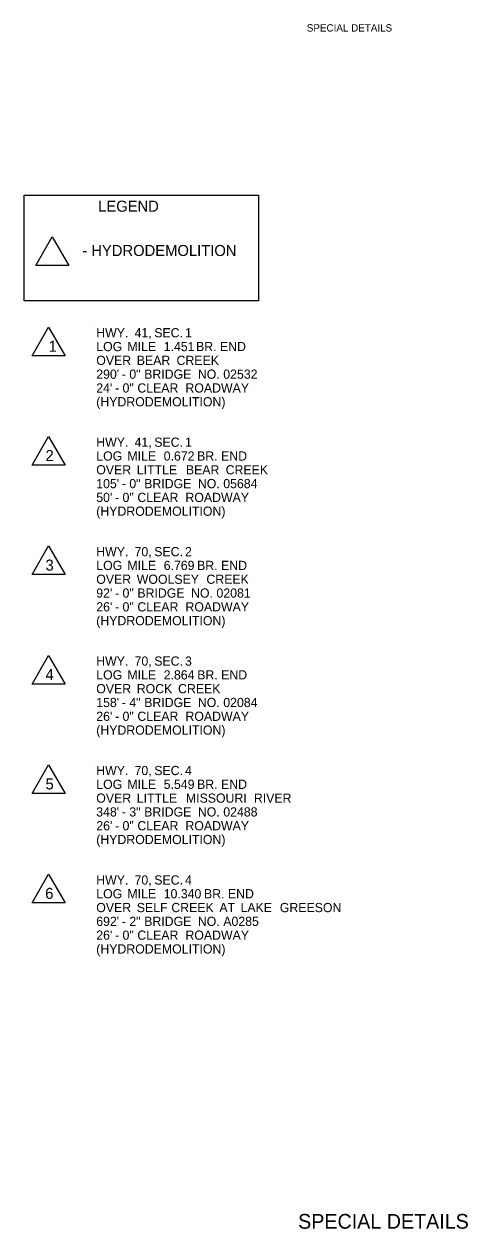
# Model space of a CAD drawing. Extents: x -17742 to 32032, y -17264 to 5867.
# Drawn here: x -5718 to -2101, y -4264 to 5557 of the extents above; entities that cross this region are included whole.
import ezdxf

# ---------------------------------------------------------------- set-up
doc = ezdxf.new("R2010")
doc.units = 0
for name, color, linetype in [('Default', 7, 'Continuous'), ('R_Annotation', 7, 'Continuous'), ('R_Border', 7, 'Continuous')]:
    doc.layers.add(name, color=color, linetype=linetype)

msp = doc.modelspace()

# ---------------------------------------------------------------- linework, layer by layer
at = {"layer": 'R_Annotation'}
for p, q in [((-5144.6, 3093.7), (-5144.6, 3093.7)), ((-5144.6, -474.8), (-5144.6, -474.8))]:
    msp.add_line(p, q, dxfattribs=at)
for points in [[(-5718.1, 4163.9), (-3807.5, 4163.9), (-3807.5, 3302.6), (-5718.1, 3302.6)], [(-5488.8, 3824.1), (-5353.8, 3590.3), (-5623.8, 3590.3)], [(-5517.9, 3087.5), (-5382.9, 2853.7), (-5652.9, 2853.7)], [(-5517.9, 2196.3), (-5382.9, 1962.5), (-5652.9, 1962.5)], [(-5517.9, 1303.3), (-5382.9, 1069.5), (-5652.9, 1069.5)], [(-5517.9, 411.2), (-5382.9, 177.3), (-5652.9, 177.3)], [(-5517.9, -481), (-5382.9, -714.8), (-5652.9, -714.8)], [(-5517.9, -1373.1), (-5382.9, -1606.9), (-5652.9, -1606.9)]]:
    msp.add_lwpolyline(points, close=True, dxfattribs=at)

# ---------------------------------------------------------------- texts
at = {"layer": 'Default'}
for s, p in [('HWY.', (-5130, 3003.7)), (' 41,', (-4845.7, 3003.7)), (' SEC.', (-4685.2, 3003.7)), (' 1', (-4434.6, 3003.7)), ('LOG', (-5130, 2891.2)), (' MILE', (-4904, 2891.2)), (' 1.451', (-4608.2, 2891.2)), (' BR.', (-4344.8, 2891.2)), (' END', (-4149.6, 2891.2)), ('OVER', (-5130, 2778.7)), (' BEAR', (-4827.6, 2778.7)), (' CREEK', (-4503.5, 2778.7)), ("290'", (-5130, 2666.2)), (' -', (-4948.5, 2666.2)), (' 0"', (-4888.3, 2666.2)), (' BRIDGE', (-4767.3, 2666.2)), (' NO.', (-4329.9, 2666.2)), (' 02532', (-4122.5, 2666.2)), ("24'", (-5130, 2553.7)), (' -', (-5003.9, 2553.7)), (' 0"', (-4943.7, 2553.7)), (' CLEAR', (-4822.7, 2553.7)), (' ROADWAY', (-4431, 2553.7)), ('(HYDRODEMOLITION)', (-5130, 2441.2)), ('HWY.', (-5130, 2111.6)), (' 41,', (-4845.7, 2111.6)), (' SEC.', (-4685.2, 2111.6)), (' 1', (-4434.6, 2111.6)), ('LOG', (-5130, 1999.1)), (' MILE', (-4904, 1999.1)), (' 0.672', (-4608.2, 1999.1)), (' BR.', (-4335.9, 1999.1)), (' END', (-4140.6, 1999.1)), ('OVER', (-5130, 1886.6)), (' LITTLE', (-4827.6, 1886.6)), (' BEAR', (-4427.3, 1886.6)), (' CREEK', (-4103.3, 1886.6)), ("105'", (-5130, 1774.1)), (' -', (-4948.5, 1774.1)), (' 0"', (-4888.3, 1774.1)), (' BRIDGE', (-4767.3, 1774.1)), (' NO.', (-4329.9, 1774.1)), (' 05684', (-4122.5, 1774.1)), ("50'", (-5130, 1661.6)), (' -', (-5003.9, 1661.6)), (' 0"', (-4943.7, 1661.6)), (' CLEAR', (-4822.7, 1661.6)), (' ROADWAY', (-4431, 1661.6)), ('(HYDRODEMOLITION)', (-5130, 1549.1)), ('HWY.', (-5130, 1219.5)), (' 70,', (-4845.7, 1219.5)), (' SEC.', (-4685.2, 1219.5)), (' 2', (-4434.6, 1219.5)), ('LOG', (-5130, 1107)), (' MILE', (-4904, 1107)), (' 6.769', (-4608.2, 1107)), (' BR.', (-4336, 1107)), (' END', (-4140.7, 1107)), ('OVER', (-5130, 994.5)), (' WOOLSEY', (-4827.6, 994.5)), (' CREEK', (-4260.1, 994.5)), ("92'", (-5130, 882)), (' -', (-5003.9, 882)), (' 0"', (-4943.7, 882)), (' BRIDGE', (-4822.7, 882)), (' NO.', (-4385.3, 882)), (' 02081', (-4177.9, 882)), ("26'", (-5130, 769.5)), (' -', (-5003.9, 769.5)), (' 0"', (-4943.7, 769.5)), (' CLEAR', (-4822.7, 769.5)), (' ROADWAY', (-4431, 769.5)), ('(HYDRODEMOLITION)', (-5130, 657)), ('HWY.', (-5130, 327.3)), (' 70,', (-4845.7, 327.3)), (' SEC.', (-4685.2, 327.3)), (' 3', (-4434.6, 327.3)), ('LOG', (-5130, 214.8)), (' MILE', (-4904, 214.8)), (' 2.864', (-4608.2, 214.8)), (' BR.', (-4335.1, 214.8)), (' END', (-4139.9, 214.8)), ('OVER', (-5130, 102.3)), (' ROCK', (-4827.6, 102.3)), (' CREEK', (-4491.2, 102.3)), ("158'", (-5130, -10.2)), (' -', (-4948.5, -10.2)), (' 4"', (-4888.3, -10.2)), (' BRIDGE', (-4767.3, -10.2)), (' NO.', (-4329.9, -10.2)), (' 02084', (-4122.5, -10.2)), ("26'", (-5130, -122.7)), (' -', (-5003.9, -122.7)), (' 0"', (-4943.7, -122.7)), (' CLEAR', (-4822.7, -122.7)), (' ROADWAY', (-4431, -122.7)), ('(HYDRODEMOLITION)', (-5130, -235.2)), ('HWY.', (-5130, -564.8)), (' 70,', (-4845.7, -564.8)), (' SEC.', (-4685.2, -564.8)), (' 4', (-4434.6, -564.8)), ('LOG', (-5130, -677.3)), (' MILE', (-4904, -677.3)), (' 5.549', (-4608.2, -677.3)), (' BR.', (-4336, -677.3)), (' END', (-4140.7, -677.3)), ('OVER', (-5130, -789.8)), (' LITTLE', (-4827.6, -789.8)), (' MISSOURI', (-4427.3, -789.8)), (' RIVER', (-3873.2, -789.8)), ("348'", (-5130, -902.3)), (' -', (-4948.5, -902.3)), (' 3"', (-4888.3, -902.3)), (' BRIDGE', (-4767.3, -902.3)), (' NO.', (-4329.9, -902.3)), (' 02488', (-4122.5, -902.3)), ("26'", (-5130, -1014.8)), (' -', (-5003.9, -1014.8)), (' 0"', (-4943.7, -1014.8)), (' CLEAR', (-4822.7, -1014.8)), (' ROADWAY', (-4431, -1014.8)), ('(HYDRODEMOLITION)', (-5130, -1127.3)), ('HWY.', (-5130, -1456.9)), (' 70,', (-4845.7, -1456.9)), (' SEC.', (-4685.2, -1456.9)), (' 4', (-4434.6, -1456.9)), ('LOG', (-5130, -1569.4)), (' MILE', (-4904, -1569.4)), (' 10.340', (-4608.2, -1569.4)), (' BR.', (-4279.8, -1569.4)), (' END', (-4084.6, -1569.4)), ('OVER', (-5130, -1681.9)), (' SELF', (-4827.6, -1681.9)), (' CREEK', (-4546, -1681.9)), (' AT', (-4154.4, -1681.9)), (' LAKE', (-3981.9, -1681.9)), (' GREESON', (-3661.6, -1681.9)), ("692'", (-5130, -1794.4)), (' -', (-4948.5, -1794.4)), (' 2"', (-4888.3, -1794.4)), (' BRIDGE', (-4767.3, -1794.4)), (' NO.', (-4329.9, -1794.4)), (' A0285', (-4122.5, -1794.4)), ("26'", (-5130, -1906.9)), (' 0"', (-4943.7, -1906.9)), (' CLEAR', (-4822.7, -1906.9)), (' ROADWAY', (-4431, -1906.9)), ('(HYDRODEMOLITION)', (-5130, -2019.4)), (' -', (-5003.9, -1906.9))]:
    msp.add_text(s, height=75, dxfattribs=at).set_placement(p)
at = {"layer": 'R_Annotation'}
for s, height, p in [('LEGEND', 90, (-5114.7, 4028)), ('- HYDRODEMOLITION', 90, (-5244, 3666.9)), ('1', 90, (-5517.9, 2886.6)), ('2', 90, (-5543.4, 1995.4)), ('3', 90, (-5543.4, 1102.4)), ('4', 90, (-5543.4, 210.3)), ('5', 90, (-5543.4, -681.9)), ('6', 90, (-5545.9, -1574)), ('SPECIAL DETAILS', 120, (-3484.9, -4262.4))]:
    msp.add_text(s, height=height, dxfattribs=at).set_placement(p)
at = {"layer": 'R_Border'}
msp.add_text('SPECIAL DETAILS', height=60, dxfattribs=at).set_placement((-3413.9, 5496.5))

doc.saveas('drawing.dxf')
